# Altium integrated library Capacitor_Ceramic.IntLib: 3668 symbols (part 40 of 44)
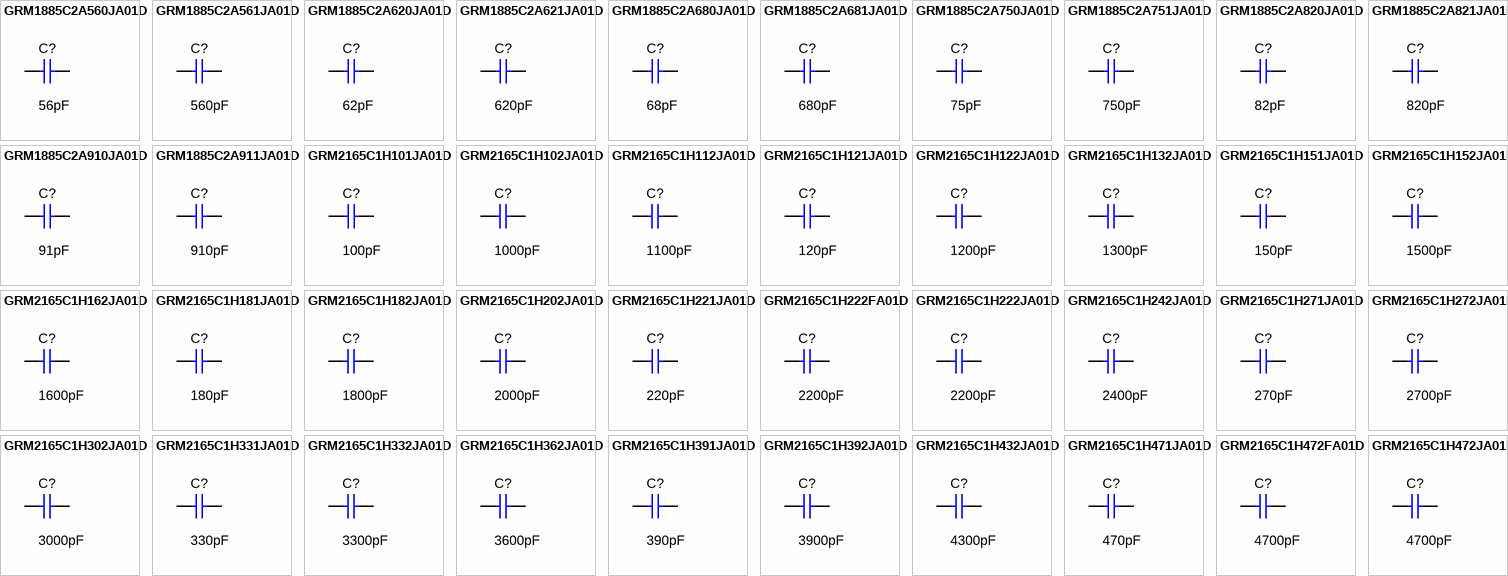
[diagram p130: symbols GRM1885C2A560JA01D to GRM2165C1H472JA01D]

## GRM2165C1H472JA01D
designator C?  ValueDisplayed: 4700pF  (hidden comment: GRM2165C1H472JA01D)
CAP, CERM, 4700 pF, 50 V,+/- 5%, C0G/NP0, 0805; Manufacturer: MuRata; Polarized: N; CompType: Capacitor; Value: 4700pF; U/M: EA; Cap_F: 0.0000000047; Tolerance_%: 5; VDC_V: 50; Value2: 50V; TaMin_C: -55; TaMax_C: 125; Cap_Case: 0805; SizeArea_mm2: 2.5; SizeAreaWB_mm2: 6.75; SizeX_mm: 2; SizeY_mm: 1.25; SizeZ_mm: 1.45; AEC Category: Q200
signal-integrity model Cap
simulation model Cap
footprint 0805_HV
footprint 0805_HV1
footprint 0805
footprint 0805M
footprint 0805L
pins: 1, 2

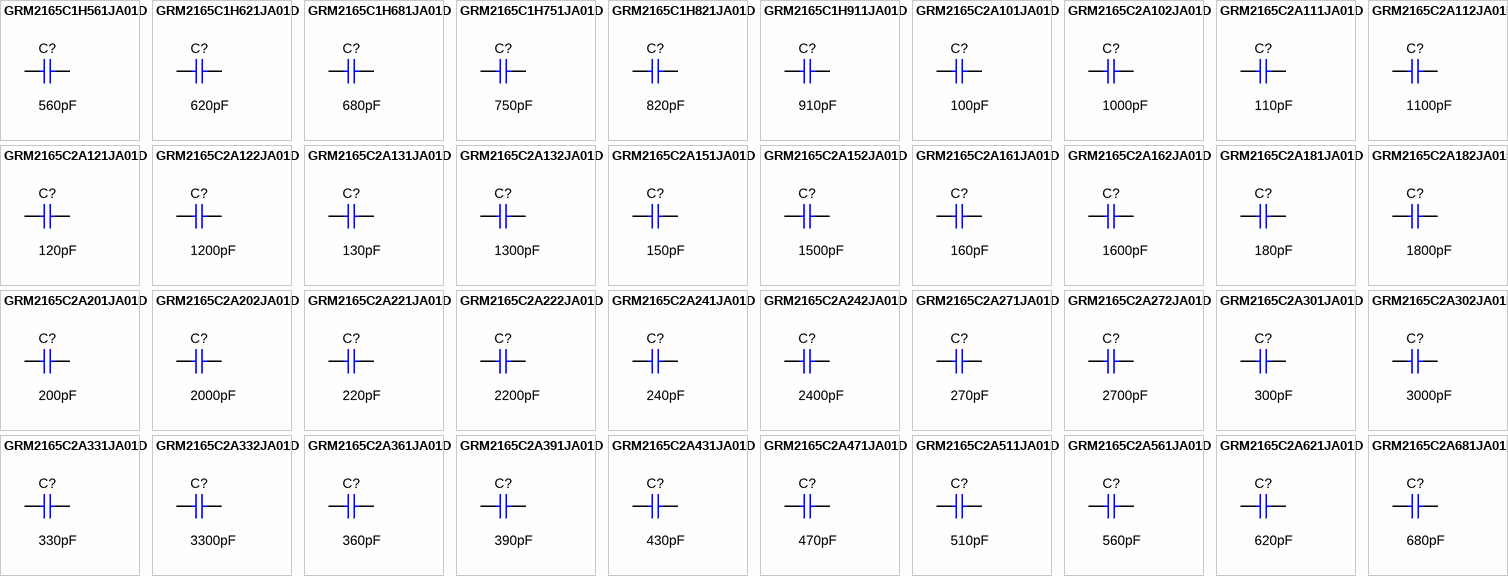
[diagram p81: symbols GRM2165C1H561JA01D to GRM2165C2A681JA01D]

## GRM2165C1H561JA01D
designator C?  ValueDisplayed: 560pF  (hidden comment: GRM2165C1H561JA01D)
CAP, CERM, 560 pF, 50 V,+/- 5%, C0G/NP0, 0805; Manufacturer: MuRata; Polarized: N; CompType: Capacitor; Value: 560pF; U/M: EA; Cap_F: 0.00000000056; Tolerance_%: 5; VDC_V: 50; Value2: 50V; TaMin_C: -55; TaMax_C: 125; Cap_Case: 0805; SizeArea_mm2: 2.5; SizeAreaWB_mm2: 6.75; SizeX_mm: 2; SizeY_mm: 1.25; SizeZ_mm: 1.45; AEC Category: Q200
signal-integrity model Cap
simulation model Cap
footprint 0805_HV
footprint 0805_HV1
footprint 0805
footprint 0805M
footprint 0805L
pins: 1, 2

## GRM2165C1H621JA01D
designator C?  ValueDisplayed: 620pF  (hidden comment: GRM2165C1H621JA01D)
CAP, CERM, 620 pF, 50 V,+/- 5%, C0G/NP0, 0805; Manufacturer: MuRata; Polarized: N; CompType: Capacitor; Value: 620pF; U/M: EA; Cap_F: 0.00000000062; Tolerance_%: 5; VDC_V: 50; Value2: 50V; TaMin_C: -55; TaMax_C: 125; Cap_Case: 0805; SizeArea_mm2: 2.5; SizeAreaWB_mm2: 6.75; SizeX_mm: 2; SizeY_mm: 1.25; SizeZ_mm: 1.45; AEC Category: Q200
signal-integrity model Cap
simulation model Cap
footprint 0805_HV
footprint 0805_HV1
footprint 0805
footprint 0805M
footprint 0805L
pins: 1, 2

## GRM2165C1H681JA01D
designator C?  ValueDisplayed: 680pF  (hidden comment: GRM2165C1H681JA01D)
CAP, CERM, 680 pF, 50 V,+/- 5%, C0G/NP0, 0805; Manufacturer: MuRata; Polarized: N; CompType: Capacitor; Value: 680pF; U/M: EA; Cap_F: 0.00000000068; Tolerance_%: 5; VDC_V: 50; Value2: 50V; TaMin_C: -55; TaMax_C: 125; Cap_Case: 0805; SizeArea_mm2: 2.5; SizeAreaWB_mm2: 6.75; SizeX_mm: 2; SizeY_mm: 1.25; SizeZ_mm: 1.45; AEC Category: Q200
signal-integrity model Cap
simulation model Cap
footprint 0805_HV
footprint 0805_HV1
footprint 0805
footprint 0805M
footprint 0805L
pins: 1, 2

## GRM2165C1H751JA01D
designator C?  ValueDisplayed: 750pF  (hidden comment: GRM2165C1H751JA01D)
CAP, CERM, 750 pF, 50 V,+/- 5%, C0G/NP0, 0805; Manufacturer: MuRata; Polarized: N; CompType: Capacitor; Value: 750pF; U/M: EA; Cap_F: 0.00000000075; Tolerance_%: 5; VDC_V: 50; Value2: 50V; TaMin_C: -55; TaMax_C: 125; Cap_Case: 0805; SizeArea_mm2: 2.5; SizeAreaWB_mm2: 6.75; SizeX_mm: 2; SizeY_mm: 1.25; SizeZ_mm: 1.45; AEC Category: Q200
signal-integrity model Cap
simulation model Cap
footprint 0805_HV
footprint 0805_HV1
footprint 0805
footprint 0805M
footprint 0805L
pins: 1, 2

## GRM2165C1H821JA01D
designator C?  ValueDisplayed: 820pF  (hidden comment: GRM2165C1H821JA01D)
CAP, CERM, 820 pF, 50 V,+/- 5%, C0G/NP0, 0805; Manufacturer: MuRata; Polarized: N; CompType: Capacitor; Value: 820pF; U/M: EA; Cap_F: 0.00000000082; Tolerance_%: 5; VDC_V: 50; Value2: 50V; TaMin_C: -55; TaMax_C: 125; Cap_Case: 0805; SizeArea_mm2: 2.5; SizeAreaWB_mm2: 6.75; SizeX_mm: 2; SizeY_mm: 1.25; SizeZ_mm: 1.45; AEC Category: Q200
signal-integrity model Cap
simulation model Cap
footprint 0805_HV
footprint 0805_HV1
footprint 0805
footprint 0805M
footprint 0805L
pins: 1, 2

## GRM2165C1H911JA01D
designator C?  ValueDisplayed: 910pF  (hidden comment: GRM2165C1H911JA01D)
CAP, CERM, 910 pF, 50 V,+/- 5%, C0G/NP0, 0805; Manufacturer: MuRata; Polarized: N; CompType: Capacitor; Value: 910pF; U/M: EA; Cap_F: 0.00000000091; Tolerance_%: 5; VDC_V: 50; Value2: 50V; TaMin_C: -55; TaMax_C: 125; Cap_Case: 0805; SizeArea_mm2: 2.5; SizeAreaWB_mm2: 6.75; SizeX_mm: 2; SizeY_mm: 1.25; SizeZ_mm: 1.45; AEC Category: Q200
signal-integrity model Cap
simulation model Cap
footprint 0805_HV
footprint 0805_HV1
footprint 0805
footprint 0805M
footprint 0805L
pins: 1, 2

## GRM2165C2A101JA01D
designator C?  ValueDisplayed: 100pF  (hidden comment: GRM2165C2A101JA01D)
CAP, CERM, 100 pF, 100 V,+/- 5%, C0G/NP0, 0805; Manufacturer: MuRata; Polarized: N; CompType: Capacitor; Value: 100pF; U/M: EA; Cap_F: 0.0000000001; Tolerance_%: 5; VDC_V: 100; Value2: 100V; TaMin_C: -55; TaMax_C: 125; Cap_Case: 0805; SizeArea_mm2: 2.5; SizeAreaWB_mm2: 6.75; SizeX_mm: 2; SizeY_mm: 1.25; SizeZ_mm: 1.45; AEC Category: Q200
signal-integrity model Cap
simulation model Cap
footprint 0805_HV
footprint 0805_HV1
footprint 0805
footprint 0805M
footprint 0805L
pins: 1, 2

## GRM2165C2A102JA01D
designator C?  ValueDisplayed: 1000pF  (hidden comment: GRM2165C2A102JA01D)
CAP, CERM, 1000 pF, 100 V,+/- 5%, C0G/NP0, 0805; Manufacturer: MuRata; Polarized: N; CompType: Capacitor; Value: 1000pF; U/M: EA; Cap_F: 0.000000001; Tolerance_%: 5; VDC_V: 100; Value2: 100V; TaMin_C: -55; TaMax_C: 125; Cap_Case: 0805; SizeArea_mm2: 2.5; SizeAreaWB_mm2: 6.75; SizeX_mm: 2; SizeY_mm: 1.25; SizeZ_mm: 1.45; AEC Category: Q200
signal-integrity model Cap
simulation model Cap
footprint 0805_HV
footprint 0805_HV1
footprint 0805
footprint 0805M
footprint 0805L
pins: 1, 2

## GRM2165C2A111JA01D
designator C?  ValueDisplayed: 110pF  (hidden comment: GRM2165C2A111JA01D)
CAP, CERM, 110 pF, 100 V,+/- 5%, C0G/NP0, 0805; Manufacturer: MuRata; Polarized: N; CompType: Capacitor; Value: 110pF; U/M: EA; Cap_F: 0.00000000011; Tolerance_%: 5; VDC_V: 100; Value2: 100V; TaMin_C: -55; TaMax_C: 125; Cap_Case: 0805; SizeArea_mm2: 2.5; SizeAreaWB_mm2: 6.75; SizeX_mm: 2; SizeY_mm: 1.25; SizeZ_mm: 1.45; AEC Category: Q200
signal-integrity model Cap
simulation model Cap
footprint 0805_HV
footprint 0805_HV1
footprint 0805
footprint 0805M
footprint 0805L
pins: 1, 2

## GRM2165C2A112JA01D
designator C?  ValueDisplayed: 1100pF  (hidden comment: GRM2165C2A112JA01D)
CAP, CERM, 1100 pF, 100 V,+/- 5%, C0G/NP0, 0805; Manufacturer: MuRata; Polarized: N; CompType: Capacitor; Value: 1100pF; U/M: EA; Cap_F: 0.0000000011; Tolerance_%: 5; VDC_V: 100; Value2: 100V; TaMin_C: -55; TaMax_C: 125; Cap_Case: 0805; SizeArea_mm2: 2.5; SizeAreaWB_mm2: 6.75; SizeX_mm: 2; SizeY_mm: 1.25; SizeZ_mm: 1.45; AEC Category: Q200
signal-integrity model Cap
simulation model Cap
footprint 0805_HV
footprint 0805_HV1
footprint 0805
footprint 0805M
footprint 0805L
pins: 1, 2

## GRM2165C2A121JA01D
designator C?  ValueDisplayed: 120pF  (hidden comment: GRM2165C2A121JA01D)
CAP, CERM, 120 pF, 100 V,+/- 5%, C0G/NP0, 0805; Manufacturer: MuRata; Polarized: N; CompType: Capacitor; Value: 120pF; U/M: EA; Cap_F: 0.00000000012; Tolerance_%: 5; VDC_V: 100; Value2: 100V; TaMin_C: -55; TaMax_C: 125; Cap_Case: 0805; SizeArea_mm2: 2.5; SizeAreaWB_mm2: 6.75; SizeX_mm: 2; SizeY_mm: 1.25; SizeZ_mm: 1.45; AEC Category: Q200
signal-integrity model Cap
simulation model Cap
footprint 0805_HV
footprint 0805_HV1
footprint 0805
footprint 0805M
footprint 0805L
pins: 1, 2

## GRM2165C2A122JA01D
designator C?  ValueDisplayed: 1200pF  (hidden comment: GRM2165C2A122JA01D)
CAP, CERM, 1200 pF, 100 V,+/- 5%, C0G/NP0, 0805; Manufacturer: MuRata; Polarized: N; CompType: Capacitor; Value: 1200pF; U/M: EA; Cap_F: 0.0000000012; Tolerance_%: 5; VDC_V: 100; Value2: 100V; TaMin_C: -55; TaMax_C: 125; Cap_Case: 0805; SizeArea_mm2: 2.5; SizeAreaWB_mm2: 6.75; SizeX_mm: 2; SizeY_mm: 1.25; SizeZ_mm: 1.45; AEC Category: Q200
signal-integrity model Cap
simulation model Cap
footprint 0805_HV
footprint 0805_HV1
footprint 0805
footprint 0805M
footprint 0805L
pins: 1, 2

## GRM2165C2A131JA01D
designator C?  ValueDisplayed: 130pF  (hidden comment: GRM2165C2A131JA01D)
CAP, CERM, 130 pF, 100 V,+/- 5%, C0G/NP0, 0805; Manufacturer: MuRata; Polarized: N; CompType: Capacitor; Value: 130pF; U/M: EA; Cap_F: 0.00000000013; Tolerance_%: 5; VDC_V: 100; Value2: 100V; TaMin_C: -55; TaMax_C: 125; Cap_Case: 0805; SizeArea_mm2: 2.5; SizeAreaWB_mm2: 6.75; SizeX_mm: 2; SizeY_mm: 1.25; SizeZ_mm: 1.45; AEC Category: Q200; Green_Lifecycle: Active; Green_REACh: Passed
signal-integrity model Cap
simulation model Cap
footprint 0805_HV
footprint 0805_HV1
footprint 0805
footprint 0805M
footprint 0805L
pins: 1, 2

## GRM2165C2A132JA01D
designator C?  ValueDisplayed: 1300pF  (hidden comment: GRM2165C2A132JA01D)
CAP, CERM, 1300 pF, 100 V,+/- 5%, C0G/NP0, 0805; Manufacturer: MuRata; Polarized: N; CompType: Capacitor; Value: 1300pF; U/M: EA; Cap_F: 0.0000000013; Tolerance_%: 5; VDC_V: 100; Value2: 100V; TaMin_C: -55; TaMax_C: 125; Cap_Case: 0805; SizeArea_mm2: 2.5; SizeAreaWB_mm2: 6.75; SizeX_mm: 2; SizeY_mm: 1.25; SizeZ_mm: 1.45; AEC Category: Q200
signal-integrity model Cap
simulation model Cap
footprint 0805_HV
footprint 0805_HV1
footprint 0805
footprint 0805M
footprint 0805L
pins: 1, 2

## GRM2165C2A151JA01D
designator C?  ValueDisplayed: 150pF  (hidden comment: GRM2165C2A151JA01D)
CAP, CERM, 150 pF, 100 V,+/- 5%, C0G/NP0, 0805; Manufacturer: MuRata; Polarized: N; CompType: Capacitor; Value: 150pF; U/M: EA; Cap_F: 0.00000000015; Tolerance_%: 5; VDC_V: 100; Value2: 100V; TaMin_C: -55; TaMax_C: 125; Cap_Case: 0805; SizeArea_mm2: 2.5; SizeAreaWB_mm2: 6.75; SizeX_mm: 2; SizeY_mm: 1.25; SizeZ_mm: 1.45; AEC Category: Q200
signal-integrity model Cap
simulation model Cap
footprint 0805_HV
footprint 0805_HV1
footprint 0805
footprint 0805M
footprint 0805L
pins: 1, 2

## GRM2165C2A152JA01D
designator C?  ValueDisplayed: 1500pF  (hidden comment: GRM2165C2A152JA01D)
CAP, CERM, 1500 pF, 100 V,+/- 5%, C0G/NP0, 0805; Manufacturer: MuRata; Polarized: N; CompType: Capacitor; Value: 1500pF; U/M: EA; Cap_F: 0.0000000015; Tolerance_%: 5; VDC_V: 100; Value2: 100V; TaMin_C: -55; TaMax_C: 125; Cap_Case: 0805; SizeArea_mm2: 2.5; SizeAreaWB_mm2: 6.75; SizeX_mm: 2; SizeY_mm: 1.25; SizeZ_mm: 1.45; AEC Category: Q200
signal-integrity model Cap
simulation model Cap
footprint 0805_HV
footprint 0805_HV1
footprint 0805
footprint 0805M
footprint 0805L
pins: 1, 2

## GRM2165C2A161JA01D
designator C?  ValueDisplayed: 160pF  (hidden comment: GRM2165C2A161JA01D)
CAP, CERM, 160 pF, 100 V,+/- 5%, C0G/NP0, 0805; Manufacturer: MuRata; Polarized: N; CompType: Capacitor; Value: 160pF; U/M: EA; Cap_F: 0.00000000016; Tolerance_%: 5; VDC_V: 100; Value2: 100V; TaMin_C: -55; TaMax_C: 125; Cap_Case: 0805; SizeArea_mm2: 2.5; SizeAreaWB_mm2: 6.75; SizeX_mm: 2; SizeY_mm: 1.25; SizeZ_mm: 1.45; AEC Category: Q200; Green_Lifecycle: Active; Green_REACh: Passed
signal-integrity model Cap
simulation model Cap
footprint 0805_HV
footprint 0805_HV1
footprint 0805
footprint 0805M
footprint 0805L
pins: 1, 2

## GRM2165C2A162JA01D
designator C?  ValueDisplayed: 1600pF  (hidden comment: GRM2165C2A162JA01D)
CAP, CERM, 1600 pF, 100 V,+/- 5%, C0G/NP0, 0805; Manufacturer: MuRata; Polarized: N; CompType: Capacitor; Value: 1600pF; U/M: EA; Cap_F: 0.0000000016; Tolerance_%: 5; VDC_V: 100; Value2: 100V; TaMin_C: -55; TaMax_C: 125; Cap_Case: 0805; SizeArea_mm2: 2.5; SizeAreaWB_mm2: 6.75; SizeX_mm: 2; SizeY_mm: 1.25; SizeZ_mm: 1.45; AEC Category: Q200
signal-integrity model Cap
simulation model Cap
footprint 0805_HV
footprint 0805_HV1
footprint 0805
footprint 0805M
footprint 0805L
pins: 1, 2

## GRM2165C2A181JA01D
designator C?  ValueDisplayed: 180pF  (hidden comment: GRM2165C2A181JA01D)
CAP, CERM, 180 pF, 100 V,+/- 5%, C0G/NP0, 0805; Manufacturer: MuRata; Polarized: N; CompType: Capacitor; Value: 180pF; U/M: EA; Cap_F: 0.00000000018; Tolerance_%: 5; VDC_V: 100; Value2: 100V; TaMin_C: -55; TaMax_C: 125; Cap_Case: 0805; SizeArea_mm2: 2.5; SizeAreaWB_mm2: 6.75; SizeX_mm: 2; SizeY_mm: 1.25; SizeZ_mm: 1.45; AEC Category: Q200
signal-integrity model Cap
simulation model Cap
footprint 0805_HV
footprint 0805_HV1
footprint 0805
footprint 0805M
footprint 0805L
pins: 1, 2

## GRM2165C2A182JA01D
designator C?  ValueDisplayed: 1800pF  (hidden comment: GRM2165C2A182JA01D)
CAP, CERM, 1800 pF, 100 V,+/- 5%, C0G/NP0, 0805; Manufacturer: MuRata; Polarized: N; CompType: Capacitor; Value: 1800pF; U/M: EA; Cap_F: 0.0000000018; Tolerance_%: 5; VDC_V: 100; Value2: 100V; TaMin_C: -55; TaMax_C: 125; Cap_Case: 0805; SizeArea_mm2: 2.5; SizeAreaWB_mm2: 6.75; SizeX_mm: 2; SizeY_mm: 1.25; SizeZ_mm: 1.45; AEC Category: Q200
signal-integrity model Cap
simulation model Cap
footprint 0805_HV
footprint 0805_HV1
footprint 0805
footprint 0805M
footprint 0805L
pins: 1, 2

## GRM2165C2A201JA01D
designator C?  ValueDisplayed: 200pF  (hidden comment: GRM2165C2A201JA01D)
CAP, CERM, 200 pF, 100 V,+/- 5%, C0G/NP0, 0805; Manufacturer: MuRata; Polarized: N; CompType: Capacitor; Value: 200pF; U/M: EA; Cap_F: 0.0000000002; Tolerance_%: 5; VDC_V: 100; Value2: 100V; TaMin_C: -55; TaMax_C: 125; Cap_Case: 0805; SizeArea_mm2: 2.5; SizeAreaWB_mm2: 6.75; SizeX_mm: 2; SizeY_mm: 1.25; SizeZ_mm: 1.45; AEC Category: Q200
signal-integrity model Cap
simulation model Cap
footprint 0805_HV
footprint 0805_HV1
footprint 0805
footprint 0805M
footprint 0805L
pins: 1, 2

## GRM2165C2A202JA01D
designator C?  ValueDisplayed: 2000pF  (hidden comment: GRM2165C2A202JA01D)
CAP, CERM, 2000 pF, 100 V,+/- 5%, C0G/NP0, 0805; Manufacturer: MuRata; Polarized: N; CompType: Capacitor; Value: 2000pF; U/M: EA; Cap_F: 0.000000002; Tolerance_%: 5; VDC_V: 100; Value2: 100V; TaMin_C: -55; TaMax_C: 125; Cap_Case: 0805; SizeArea_mm2: 2.5; SizeAreaWB_mm2: 6.75; SizeX_mm: 2; SizeY_mm: 1.25; SizeZ_mm: 1.45; AEC Category: Q200
signal-integrity model Cap
simulation model Cap
footprint 0805_HV
footprint 0805_HV1
footprint 0805
footprint 0805M
footprint 0805L
pins: 1, 2

## GRM2165C2A221JA01D
designator C?  ValueDisplayed: 220pF  (hidden comment: GRM2165C2A221JA01D)
CAP, CERM, 220 pF, 100 V,+/- 5%, C0G/NP0, 0805; Manufacturer: MuRata; Polarized: N; CompType: Capacitor; Value: 220pF; U/M: EA; Cap_F: 0.00000000022; Tolerance_%: 5; VDC_V: 100; Value2: 100V; TaMin_C: -55; TaMax_C: 125; Cap_Case: 0805; SizeArea_mm2: 2.5; SizeAreaWB_mm2: 6.75; SizeX_mm: 2; SizeY_mm: 1.25; SizeZ_mm: 1.45; AEC Category: Q200
signal-integrity model Cap
simulation model Cap
footprint 0805_HV
footprint 0805_HV1
footprint 0805
footprint 0805M
footprint 0805L
pins: 1, 2

## GRM2165C2A222JA01D
designator C?  ValueDisplayed: 2200pF  (hidden comment: GRM2165C2A222JA01D)
CAP, CERM, 2200 pF, 100 V,+/- 5%, C0G/NP0, 0805; Manufacturer: MuRata; Polarized: N; CompType: Capacitor; Value: 2200pF; U/M: EA; Cap_F: 0.0000000022; Tolerance_%: 5; VDC_V: 100; Value2: 100V; TaMin_C: -55; TaMax_C: 125; Cap_Case: 0805; SizeArea_mm2: 2.5; SizeAreaWB_mm2: 6.75; SizeX_mm: 2; SizeY_mm: 1.25; SizeZ_mm: 1.45; AEC Category: Q200
signal-integrity model Cap
simulation model Cap
footprint 0805_HV
footprint 0805_HV1
footprint 0805
footprint 0805M
footprint 0805L
pins: 1, 2

## GRM2165C2A241JA01D
designator C?  ValueDisplayed: 240pF  (hidden comment: GRM2165C2A241JA01D)
CAP, CERM, 240 pF, 100 V,+/- 5%, C0G/NP0, 0805; Manufacturer: MuRata; Polarized: N; CompType: Capacitor; Value: 240pF; U/M: EA; Cap_F: 0.00000000024; Tolerance_%: 5; VDC_V: 100; Value2: 100V; TaMin_C: -55; TaMax_C: 125; Cap_Case: 0805; SizeArea_mm2: 2.5; SizeAreaWB_mm2: 6.75; SizeX_mm: 2; SizeY_mm: 1.25; SizeZ_mm: 1.45; AEC Category: Q200
signal-integrity model Cap
simulation model Cap
footprint 0805_HV
footprint 0805_HV1
footprint 0805
footprint 0805M
footprint 0805L
pins: 1, 2

## GRM2165C2A242JA01D
designator C?  ValueDisplayed: 2400pF  (hidden comment: GRM2165C2A242JA01D)
CAP, CERM, 2400 pF, 100 V,+/- 5%, C0G/NP0, 0805; Manufacturer: MuRata; Polarized: N; CompType: Capacitor; Value: 2400pF; U/M: EA; Cap_F: 0.0000000024; Tolerance_%: 5; VDC_V: 100; Value2: 100V; TaMin_C: -55; TaMax_C: 125; Cap_Case: 0805; SizeArea_mm2: 2.5; SizeAreaWB_mm2: 6.75; SizeX_mm: 2; SizeY_mm: 1.25; SizeZ_mm: 1.45; AEC Category: Q200
signal-integrity model Cap
simulation model Cap
footprint 0805_HV
footprint 0805_HV1
footprint 0805
footprint 0805M
footprint 0805L
pins: 1, 2

## GRM2165C2A271JA01D
designator C?  ValueDisplayed: 270pF  (hidden comment: GRM2165C2A271JA01D)
CAP, CERM, 270 pF, 100 V,+/- 5%, C0G/NP0, 0805; Manufacturer: MuRata; Polarized: N; CompType: Capacitor; Value: 270pF; U/M: EA; Cap_F: 0.00000000027; Tolerance_%: 5; VDC_V: 100; Value2: 100V; TaMin_C: -55; TaMax_C: 125; Cap_Case: 0805; SizeArea_mm2: 2.5; SizeAreaWB_mm2: 6.75; SizeX_mm: 2; SizeY_mm: 1.25; SizeZ_mm: 1.45; AEC Category: Q200
signal-integrity model Cap
simulation model Cap
footprint 0805_HV
footprint 0805_HV1
footprint 0805
footprint 0805M
footprint 0805L
pins: 1, 2

## GRM2165C2A272JA01D
designator C?  ValueDisplayed: 2700pF  (hidden comment: GRM2165C2A272JA01D)
CAP, CERM, 2700 pF, 100 V,+/- 5%, C0G/NP0, 0805; Manufacturer: MuRata; Polarized: N; CompType: Capacitor; Value: 2700pF; U/M: EA; Cap_F: 0.0000000027; Tolerance_%: 5; VDC_V: 100; Value2: 100V; TaMin_C: -55; TaMax_C: 125; Cap_Case: 0805; SizeArea_mm2: 2.5; SizeAreaWB_mm2: 6.75; SizeX_mm: 2; SizeY_mm: 1.25; SizeZ_mm: 1.45; AEC Category: Q200
signal-integrity model Cap
simulation model Cap
footprint 0805_HV
footprint 0805_HV1
footprint 0805
footprint 0805M
footprint 0805L
pins: 1, 2

## GRM2165C2A301JA01D
designator C?  ValueDisplayed: 300pF  (hidden comment: GRM2165C2A301JA01D)
CAP, CERM, 300 pF, 100 V,+/- 5%, C0G/NP0, 0805; Manufacturer: MuRata; Polarized: N; CompType: Capacitor; Value: 300pF; U/M: EA; Cap_F: 0.0000000003; Tolerance_%: 5; VDC_V: 100; Value2: 100V; TaMin_C: -55; TaMax_C: 125; Cap_Case: 0805; SizeArea_mm2: 2.5; SizeAreaWB_mm2: 6.75; SizeX_mm: 2; SizeY_mm: 1.25; SizeZ_mm: 1.45; AEC Category: Q200
signal-integrity model Cap
simulation model Cap
footprint 0805_HV
footprint 0805_HV1
footprint 0805
footprint 0805M
footprint 0805L
pins: 1, 2

## GRM2165C2A302JA01D
designator C?  ValueDisplayed: 3000pF  (hidden comment: GRM2165C2A302JA01D)
CAP, CERM, 3000 pF, 100 V,+/- 5%, C0G/NP0, 0805; Manufacturer: MuRata; Polarized: N; CompType: Capacitor; Value: 3000pF; U/M: EA; Cap_F: 0.000000003; Tolerance_%: 5; VDC_V: 100; Value2: 100V; TaMin_C: -55; TaMax_C: 125; Cap_Case: 0805; SizeArea_mm2: 2.5; SizeAreaWB_mm2: 6.75; SizeX_mm: 2; SizeY_mm: 1.25; SizeZ_mm: 1.45; AEC Category: Q200
signal-integrity model Cap
simulation model Cap
footprint 0805_HV
footprint 0805_HV1
footprint 0805
footprint 0805M
footprint 0805L
pins: 1, 2

## GRM2165C2A331JA01D
designator C?  ValueDisplayed: 330pF  (hidden comment: GRM2165C2A331JA01D)
CAP, CERM, 330 pF, 100 V,+/- 5%, C0G/NP0, 0805; Manufacturer: MuRata; Polarized: N; CompType: Capacitor; Value: 330pF; U/M: EA; Cap_F: 0.00000000033; Tolerance_%: 5; VDC_V: 100; Value2: 100V; TaMin_C: -55; TaMax_C: 125; Cap_Case: 0805; SizeArea_mm2: 2.5; SizeAreaWB_mm2: 6.75; SizeX_mm: 2; SizeY_mm: 1.25; SizeZ_mm: 1.45; AEC Category: Q200
signal-integrity model Cap
simulation model Cap
footprint 0805_HV
footprint 0805_HV1
footprint 0805
footprint 0805M
footprint 0805L
pins: 1, 2

## GRM2165C2A332JA01D
designator C?  ValueDisplayed: 3300pF  (hidden comment: GRM2165C2A332JA01D)
CAP, CERM, 3300 pF, 100 V,+/- 5%, C0G/NP0, 0805; Manufacturer: MuRata; Polarized: N; CompType: Capacitor; Value: 3300pF; U/M: EA; Cap_F: 0.0000000033; Tolerance_%: 5; VDC_V: 100; Value2: 100V; TaMin_C: -55; TaMax_C: 125; Cap_Case: 0805; SizeArea_mm2: 2.5; SizeAreaWB_mm2: 6.75; SizeX_mm: 2; SizeY_mm: 1.25; SizeZ_mm: 1.45; AEC Category: Q200
signal-integrity model Cap
simulation model Cap
footprint 0805_HV
footprint 0805_HV1
footprint 0805
footprint 0805M
footprint 0805L
pins: 1, 2

## GRM2165C2A361JA01D
designator C?  ValueDisplayed: 360pF  (hidden comment: GRM2165C2A361JA01D)
CAP, CERM, 360 pF, 100 V,+/- 5%, C0G/NP0, 0805; Manufacturer: MuRata; Polarized: N; CompType: Capacitor; Value: 360pF; U/M: EA; Cap_F: 0.00000000036; Tolerance_%: 5; VDC_V: 100; Value2: 100V; TaMin_C: -55; TaMax_C: 125; Cap_Case: 0805; SizeArea_mm2: 2.5; SizeAreaWB_mm2: 6.75; SizeX_mm: 2; SizeY_mm: 1.25; SizeZ_mm: 1.45; AEC Category: Q200
signal-integrity model Cap
simulation model Cap
footprint 0805_HV
footprint 0805_HV1
footprint 0805
footprint 0805M
footprint 0805L
pins: 1, 2

## GRM2165C2A391JA01D
designator C?  ValueDisplayed: 390pF  (hidden comment: GRM2165C2A391JA01D)
CAP, CERM, 390 pF, 100 V,+/- 5%, C0G/NP0, 0805; Manufacturer: MuRata; Polarized: N; CompType: Capacitor; Value: 390pF; U/M: EA; Cap_F: 0.00000000039; Tolerance_%: 5; VDC_V: 100; Value2: 100V; TaMin_C: -55; TaMax_C: 125; Cap_Case: 0805; SizeArea_mm2: 2.5; SizeAreaWB_mm2: 6.75; SizeX_mm: 2; SizeY_mm: 1.25; SizeZ_mm: 1.45; AEC Category: Q200
signal-integrity model Cap
simulation model Cap
footprint 0805_HV
footprint 0805_HV1
footprint 0805
footprint 0805M
footprint 0805L
pins: 1, 2

## GRM2165C2A431JA01D
designator C?  ValueDisplayed: 430pF  (hidden comment: GRM2165C2A431JA01D)
CAP, CERM, 430 pF, 100 V,+/- 5%, C0G/NP0, 0805; Manufacturer: MuRata; Polarized: N; CompType: Capacitor; Value: 430pF; U/M: EA; Cap_F: 0.00000000043; Tolerance_%: 5; VDC_V: 100; Value2: 100V; TaMin_C: -55; TaMax_C: 125; Cap_Case: 0805; SizeArea_mm2: 2.5; SizeAreaWB_mm2: 6.75; SizeX_mm: 2; SizeY_mm: 1.25; SizeZ_mm: 1.45; AEC Category: Q200
signal-integrity model Cap
simulation model Cap
footprint 0805_HV
footprint 0805_HV1
footprint 0805
footprint 0805M
footprint 0805L
pins: 1, 2

## GRM2165C2A471JA01D
designator C?  ValueDisplayed: 470pF  (hidden comment: GRM2165C2A471JA01D)
CAP, CERM, 470 pF, 100 V,+/- 5%, C0G/NP0, 0805; Manufacturer: MuRata; Polarized: N; CompType: Capacitor; Value: 470pF; U/M: EA; Cap_F: 0.00000000047; Tolerance_%: 5; VDC_V: 100; Value2: 100V; TaMin_C: -55; TaMax_C: 125; Cap_Case: 0805; SizeArea_mm2: 2.5; SizeAreaWB_mm2: 6.75; SizeX_mm: 2; SizeY_mm: 1.25; SizeZ_mm: 1.45; AEC Category: Q200; Green_Lifecycle: Active; Green_REACh: Passed
signal-integrity model Cap
simulation model Cap
footprint 0805_HV
footprint 0805_HV1
footprint 0805
footprint 0805M
footprint 0805L
pins: 1, 2

## GRM2165C2A511JA01D
designator C?  ValueDisplayed: 510pF  (hidden comment: GRM2165C2A511JA01D)
CAP, CERM, 510 pF, 100 V,+/- 5%, C0G/NP0, 0805; Manufacturer: MuRata; Polarized: N; CompType: Capacitor; Value: 510pF; U/M: EA; Cap_F: 0.00000000051; Tolerance_%: 5; VDC_V: 100; Value2: 100V; TaMin_C: -55; TaMax_C: 125; Cap_Case: 0805; SizeArea_mm2: 2.5; SizeAreaWB_mm2: 6.75; SizeX_mm: 2; SizeY_mm: 1.25; SizeZ_mm: 1.45; AEC Category: Q200
signal-integrity model Cap
simulation model Cap
footprint 0805_HV
footprint 0805_HV1
footprint 0805
footprint 0805M
footprint 0805L
pins: 1, 2

## GRM2165C2A561JA01D
designator C?  ValueDisplayed: 560pF  (hidden comment: GRM2165C2A561JA01D)
CAP, CERM, 560 pF, 100 V,+/- 5%, C0G/NP0, 0805; Manufacturer: MuRata; Polarized: N; CompType: Capacitor; Value: 560pF; U/M: EA; Cap_F: 0.00000000056; Tolerance_%: 5; VDC_V: 100; Value2: 100V; TaMin_C: -55; TaMax_C: 125; Cap_Case: 0805; SizeArea_mm2: 2.5; SizeAreaWB_mm2: 6.75; SizeX_mm: 2; SizeY_mm: 1.25; SizeZ_mm: 1.45; AEC Category: Q200
signal-integrity model Cap
simulation model Cap
footprint 0805_HV
footprint 0805_HV1
footprint 0805
footprint 0805M
footprint 0805L
pins: 1, 2

## GRM2165C2A621JA01D
designator C?  ValueDisplayed: 620pF  (hidden comment: GRM2165C2A621JA01D)
CAP, CERM, 620 pF, 100 V,+/- 5%, C0G/NP0, 0805; Manufacturer: MuRata; Polarized: N; CompType: Capacitor; Value: 620pF; U/M: EA; Cap_F: 0.00000000062; Tolerance_%: 5; VDC_V: 100; Value2: 100V; TaMin_C: -55; TaMax_C: 125; Cap_Case: 0805; SizeArea_mm2: 2.5; SizeAreaWB_mm2: 6.75; SizeX_mm: 2; SizeY_mm: 1.25; SizeZ_mm: 1.45; AEC Category: Q200
signal-integrity model Cap
simulation model Cap
footprint 0805_HV
footprint 0805_HV1
footprint 0805
footprint 0805M
footprint 0805L
pins: 1, 2

## GRM2165C2A681JA01D
designator C?  ValueDisplayed: 680pF  (hidden comment: GRM2165C2A681JA01D)
CAP, CERM, 680 pF, 100 V,+/- 5%, C0G/NP0, 0805; Manufacturer: MuRata; Polarized: N; CompType: Capacitor; Value: 680pF; U/M: EA; Cap_F: 0.00000000068; Tolerance_%: 5; VDC_V: 100; Value2: 100V; TaMin_C: -55; TaMax_C: 125; Cap_Case: 0805; SizeArea_mm2: 2.5; SizeAreaWB_mm2: 6.75; SizeX_mm: 2; SizeY_mm: 1.25; SizeZ_mm: 1.45; AEC Category: Q200
signal-integrity model Cap
simulation model Cap
footprint 0805_HV
footprint 0805_HV1
footprint 0805
footprint 0805M
footprint 0805L
pins: 1, 2

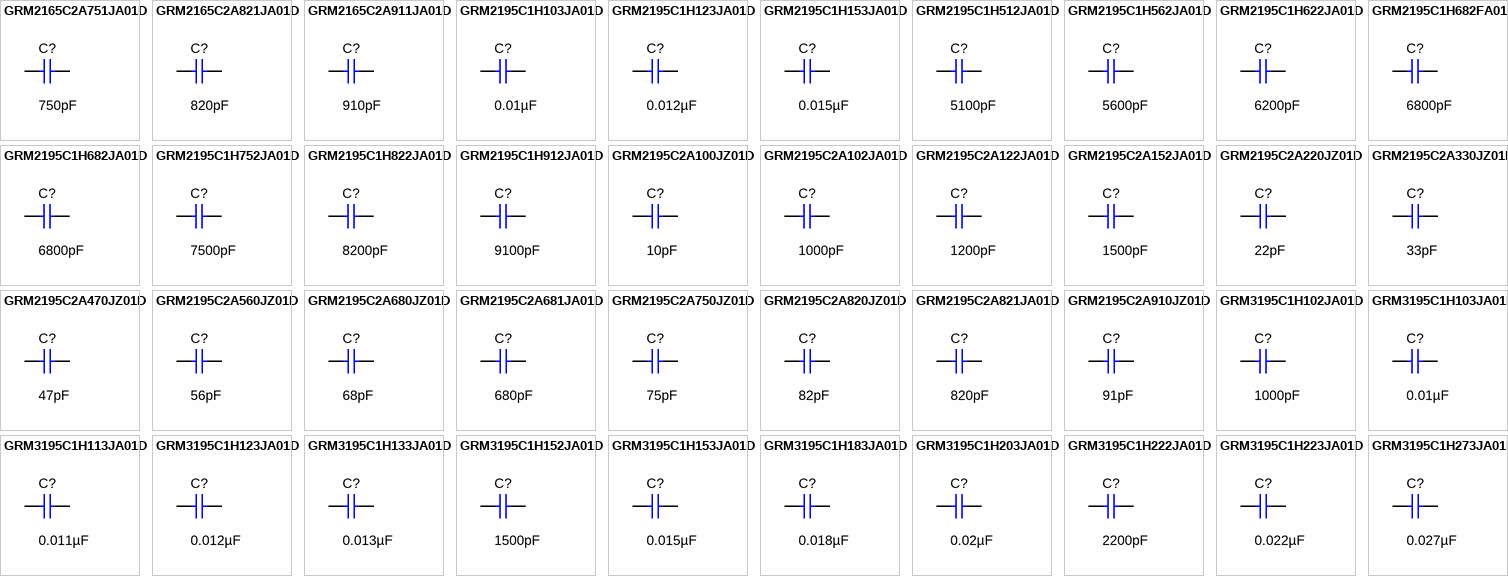
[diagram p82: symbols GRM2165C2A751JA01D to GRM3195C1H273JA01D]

## GRM2165C2A751JA01D
designator C?  ValueDisplayed: 750pF  (hidden comment: GRM2165C2A751JA01D)
CAP, CERM, 750 pF, 100 V,+/- 5%, C0G/NP0, 0805; Manufacturer: MuRata; Polarized: N; CompType: Capacitor; Value: 750pF; U/M: EA; Cap_F: 0.00000000075; Tolerance_%: 5; VDC_V: 100; Value2: 100V; TaMin_C: -55; TaMax_C: 125; Cap_Case: 0805; SizeArea_mm2: 2.5; SizeAreaWB_mm2: 6.75; SizeX_mm: 2; SizeY_mm: 1.25; SizeZ_mm: 1.45; AEC Category: Q200
signal-integrity model Cap
simulation model Cap
footprint 0805_HV
footprint 0805_HV1
footprint 0805
footprint 0805M
footprint 0805L
pins: 1, 2

## GRM2165C2A821JA01D
designator C?  ValueDisplayed: 820pF  (hidden comment: GRM2165C2A821JA01D)
CAP, CERM, 820 pF, 100 V,+/- 5%, C0G/NP0, 0805; Manufacturer: MuRata; Polarized: N; CompType: Capacitor; Value: 820pF; U/M: EA; Cap_F: 0.00000000082; Tolerance_%: 5; VDC_V: 100; Value2: 100V; TaMin_C: -55; TaMax_C: 125; Cap_Case: 0805; SizeArea_mm2: 2.5; SizeAreaWB_mm2: 6.75; SizeX_mm: 2; SizeY_mm: 1.25; SizeZ_mm: 1.45; AEC Category: Q200
signal-integrity model Cap
simulation model Cap
footprint 0805_HV
footprint 0805_HV1
footprint 0805
footprint 0805M
footprint 0805L
pins: 1, 2

## GRM2165C2A911JA01D
designator C?  ValueDisplayed: 910pF  (hidden comment: GRM2165C2A911JA01D)
CAP, CERM, 910 pF, 100 V,+/- 5%, C0G/NP0, 0805; Manufacturer: MuRata; Polarized: N; CompType: Capacitor; Value: 910pF; U/M: EA; Cap_F: 0.00000000091; Tolerance_%: 5; VDC_V: 100; Value2: 100V; TaMin_C: -55; TaMax_C: 125; Cap_Case: 0805; SizeArea_mm2: 2.5; SizeAreaWB_mm2: 6.75; SizeX_mm: 2; SizeY_mm: 1.25; SizeZ_mm: 1.45; AEC Category: Q200
signal-integrity model Cap
simulation model Cap
footprint 0805_HV
footprint 0805_HV1
footprint 0805
footprint 0805M
footprint 0805L
pins: 1, 2

## GRM2195C1H103JA01D
designator C?  ValueDisplayed: 0.01µF  (hidden comment: GRM2195C1H103JA01D)
CAP, CERM, 0.01 µF, 50 V,+/- 5%, C0G/NP0, 0805; Manufacturer: MuRata; Polarized: N; CompType: Capacitor; Value: 0.01uF; U/M: EA; Cap_F: 0.00000001; Tolerance_%: 5; VDC_V: 50; Value2: 50V; TaMin_C: -55; TaMax_C: 125; Cap_Case: 0805; SizeArea_mm2: 2.5; SizeAreaWB_mm2: 6.75; SizeX_mm: 2; SizeY_mm: 1.25; SizeZ_mm: 1.45; AEC Category: Q200; Green_Lifecycle: Active; Green_REACh: Passed
signal-integrity model Cap
simulation model Cap
footprint 0805_HV
footprint 0805_HV1
footprint 0805
footprint 0805M
footprint 0805L
pins: 1, 2

## GRM2195C1H123JA01D
designator C?  ValueDisplayed: 0.012µF  (hidden comment: GRM2195C1H123JA01D)
CAP, CERM, 0.012 µF, 50 V,+/- 5%, C0G/NP0, 0805; Manufacturer: MuRata; Polarized: N; CompType: Capacitor; Value: 0.012uF; U/M: EA; Cap_F: 0.000000012; Tolerance_%: 5; VDC_V: 50; Value2: 50V; TaMin_C: -55; TaMax_C: 125; Cap_Case: 0805; SizeArea_mm2: 2.5; SizeAreaWB_mm2: 6.75; SizeX_mm: 2; SizeY_mm: 1.25; SizeZ_mm: 1.45; AEC Category: Q200
signal-integrity model Cap
simulation model Cap
footprint 0805_HV
footprint 0805_HV1
footprint 0805
footprint 0805M
footprint 0805L
pins: 1, 2

## GRM2195C1H153JA01D
designator C?  ValueDisplayed: 0.015µF  (hidden comment: GRM2195C1H153JA01D)
CAP, CERM, 0.015 µF, 50 V,+/- 5%, C0G/NP0, 0805; Manufacturer: MuRata; Polarized: N; CompType: Capacitor; Value: 0.015uF; U/M: EA; Cap_F: 0.000000015; Tolerance_%: 5; VDC_V: 50; Value2: 50V; TaMin_C: -55; TaMax_C: 125; Cap_Case: 0805; SizeArea_mm2: 2.5; SizeAreaWB_mm2: 6.75; SizeX_mm: 2; SizeY_mm: 1.25; SizeZ_mm: 1.45; AEC Category: Q200
signal-integrity model Cap
simulation model Cap
footprint 0805_HV
footprint 0805_HV1
footprint 0805
footprint 0805M
footprint 0805L
pins: 1, 2

## GRM2195C1H512JA01D
designator C?  ValueDisplayed: 5100pF  (hidden comment: GRM2195C1H512JA01D)
CAP, CERM, 5100 pF, 50 V,+/- 5%, C0G/NP0, 0805; Manufacturer: MuRata; Polarized: N; CompType: Capacitor; Value: 5100pF; U/M: EA; Cap_F: 0.0000000051; Tolerance_%: 5; VDC_V: 50; Value2: 50V; TaMin_C: -55; TaMax_C: 125; Cap_Case: 0805; SizeArea_mm2: 2.5; SizeAreaWB_mm2: 6.75; SizeX_mm: 2; SizeY_mm: 1.25; SizeZ_mm: 1.45; AEC Category: Q200
signal-integrity model Cap
simulation model Cap
footprint 0805_HV
footprint 0805_HV1
footprint 0805
footprint 0805M
footprint 0805L
pins: 1, 2

## GRM2195C1H562JA01D
designator C?  ValueDisplayed: 5600pF  (hidden comment: GRM2195C1H562JA01D)
CAP, CERM, 5600 pF, 50 V,+/- 5%, C0G/NP0, 0805; Manufacturer: MuRata; Polarized: N; CompType: Capacitor; Value: 5600pF; U/M: EA; Cap_F: 0.0000000056; Tolerance_%: 5; VDC_V: 50; Value2: 50V; TaMin_C: -55; TaMax_C: 125; Cap_Case: 0805; SizeArea_mm2: 2.5; SizeAreaWB_mm2: 6.75; SizeX_mm: 2; SizeY_mm: 1.25; SizeZ_mm: 1.45; AEC Category: Q200
signal-integrity model Cap
simulation model Cap
footprint 0805_HV
footprint 0805_HV1
footprint 0805
footprint 0805M
footprint 0805L
pins: 1, 2

## GRM2195C1H622JA01D
designator C?  ValueDisplayed: 6200pF  (hidden comment: GRM2195C1H622JA01D)
CAP, CERM, 6200 pF, 50 V,+/- 5%, C0G/NP0, 0805; Manufacturer: MuRata; Polarized: N; CompType: Capacitor; Value: 6200pF; U/M: EA; Cap_F: 0.0000000062; Tolerance_%: 5; VDC_V: 50; Value2: 50V; TaMin_C: -55; TaMax_C: 125; Cap_Case: 0805; SizeArea_mm2: 2.5; SizeAreaWB_mm2: 6.75; SizeX_mm: 2; SizeY_mm: 1.25; SizeZ_mm: 1.45; AEC Category: Q200
signal-integrity model Cap
simulation model Cap
footprint 0805_HV
footprint 0805_HV1
footprint 0805
footprint 0805M
footprint 0805L
pins: 1, 2

## GRM2195C1H682FA01D
designator C?  ValueDisplayed: 6800pF  (hidden comment: GRM2195C1H682FA01D)
CAP, CERM, 6800 pF, 50 V,+/- 1%, C0G/NP0, 0805; Manufacturer: MuRata; Polarized: N; CompType: Capacitor; Value: 6800pF; U/M: EA; Cap_F: 0.0000000068; Tolerance_%: 1; VDC_V: 50; Value2: 50V; TaMin_C: -55; TaMax_C: 125; Cap_Case: 0805; SizeArea_mm2: 2.5; SizeAreaWB_mm2: 6.75; SizeX_mm: 2; SizeY_mm: 1.25; SizeZ_mm: 1.45; AEC Category: Q200
signal-integrity model Cap
simulation model Cap
footprint 0805_HV
footprint 0805_HV1
footprint 0805
footprint 0805M
footprint 0805L
pins: 1, 2

## GRM2195C1H682JA01D
designator C?  ValueDisplayed: 6800pF  (hidden comment: GRM2195C1H682JA01D)
CAP, CERM, 6800 pF, 50 V,+/- 5%, C0G/NP0, 0805; Manufacturer: MuRata; Polarized: N; CompType: Capacitor; Value: 6800pF; U/M: EA; Cap_F: 0.0000000068; Tolerance_%: 5; VDC_V: 50; Value2: 50V; TaMin_C: -55; TaMax_C: 125; Cap_Case: 0805; SizeArea_mm2: 2.5; SizeAreaWB_mm2: 6.75; SizeX_mm: 2; SizeY_mm: 1.25; SizeZ_mm: 1.45; AEC Category: Q200
signal-integrity model Cap
simulation model Cap
footprint 0805_HV
footprint 0805_HV1
footprint 0805
footprint 0805M
footprint 0805L
pins: 1, 2

## GRM2195C1H752JA01D
designator C?  ValueDisplayed: 7500pF  (hidden comment: GRM2195C1H752JA01D)
CAP, CERM, 7500 pF, 50 V,+/- 5%, C0G/NP0, 0805; Manufacturer: MuRata; Polarized: N; CompType: Capacitor; Value: 7500pF; U/M: EA; Cap_F: 0.0000000075; Tolerance_%: 5; VDC_V: 50; Value2: 50V; TaMin_C: -55; TaMax_C: 125; Cap_Case: 0805; SizeArea_mm2: 2.5; SizeAreaWB_mm2: 6.75; SizeX_mm: 2; SizeY_mm: 1.25; SizeZ_mm: 1.45; AEC Category: Q200
signal-integrity model Cap
simulation model Cap
footprint 0805_HV
footprint 0805_HV1
footprint 0805
footprint 0805M
footprint 0805L
pins: 1, 2

## GRM2195C1H822JA01D
designator C?  ValueDisplayed: 8200pF  (hidden comment: GRM2195C1H822JA01D)
CAP, CERM, 8200 pF, 50 V,+/- 5%, C0G/NP0, 0805; Manufacturer: MuRata; Polarized: N; CompType: Capacitor; Value: 8200pF; U/M: EA; Cap_F: 0.0000000082; Tolerance_%: 5; VDC_V: 50; Value2: 50V; TaMin_C: -55; TaMax_C: 125; Cap_Case: 0805; SizeArea_mm2: 2.5; SizeAreaWB_mm2: 6.75; SizeX_mm: 2; SizeY_mm: 1.25; SizeZ_mm: 1.45; AEC Category: Q200
signal-integrity model Cap
simulation model Cap
footprint 0805_HV
footprint 0805_HV1
footprint 0805
footprint 0805M
footprint 0805L
pins: 1, 2

## GRM2195C1H912JA01D
designator C?  ValueDisplayed: 9100pF  (hidden comment: GRM2195C1H912JA01D)
CAP, CERM, 9100 pF, 50 V,+/- 5%, C0G/NP0, 0805; Manufacturer: MuRata; Polarized: N; CompType: Capacitor; Value: 9100pF; U/M: EA; Cap_F: 0.0000000091; Tolerance_%: 5; VDC_V: 50; Value2: 50V; TaMin_C: -55; TaMax_C: 125; Cap_Case: 0805; SizeArea_mm2: 2.5; SizeAreaWB_mm2: 6.75; SizeX_mm: 2; SizeY_mm: 1.25; SizeZ_mm: 1.45; AEC Category: Q200
signal-integrity model Cap
simulation model Cap
footprint 0805_HV
footprint 0805_HV1
footprint 0805
footprint 0805M
footprint 0805L
pins: 1, 2

## GRM2195C2A100JZ01D
designator C?  ValueDisplayed: 10pF  (hidden comment: GRM2195C2A100JZ01D)
CAP, CERM, 10 pF, 100 V,+/- 5%, C0G/NP0, 0805; Manufacturer: MuRata; Polarized: N; CompType: Capacitor; Value: 10pF; U/M: EA; Cap_F: 0.00000000001; Tolerance_%: 5; VDC_V: 100; Value2: 100V; TaMin_C: -55; TaMax_C: 125; Cap_Case: 0805; SizeArea_mm2: 2.5; SizeAreaWB_mm2: 6.75; SizeX_mm: 2; SizeY_mm: 1.25; SizeZ_mm: 1.45; AEC Category: Q200
signal-integrity model Cap
simulation model Cap
footprint 0805_HV
footprint 0805_HV1
footprint 0805
footprint 0805M
footprint 0805L
pins: 1, 2

## GRM2195C2A102JA01D
designator C?  ValueDisplayed: 1000pF  (hidden comment: GRM2195C2A102JA01D)
CAP, CERM, 1000 pF, 100 V,+/- 5%, C0G/NP0, 0805; Manufacturer: MuRata; Polarized: N; CompType: Capacitor; Value: 1000pF; U/M: EA; Cap_F: 0.000000001; Tolerance_%: 5; VDC_V: 100; Value2: 100V; TaMin_C: -55; TaMax_C: 125; Cap_Case: 0805; SizeArea_mm2: 2.5; SizeAreaWB_mm2: 6.75; SizeX_mm: 2; SizeY_mm: 1.25; SizeZ_mm: 1.45; AEC Category: Q200; Green_Lifecycle: Active; Green_REACh: Passed
signal-integrity model Cap
simulation model Cap
footprint 0805_HV
footprint 0805_HV1
footprint 0805
footprint 0805M
footprint 0805L
pins: 1, 2

## GRM2195C2A122JA01D
designator C?  ValueDisplayed: 1200pF  (hidden comment: GRM2195C2A122JA01D)
CAP, CERM, 1200 pF, 100 V,+/- 5%, C0G/NP0, 0805; Manufacturer: MuRata; Polarized: N; CompType: Capacitor; Value: 1200pF; U/M: EA; Cap_F: 0.0000000012; Tolerance_%: 5; VDC_V: 100; Value2: 100V; TaMin_C: -55; TaMax_C: 125; Cap_Case: 0805; SizeArea_mm2: 2.5; SizeAreaWB_mm2: 6.75; SizeX_mm: 2; SizeY_mm: 1.25; SizeZ_mm: 1.45; AEC Category: Q200
signal-integrity model Cap
simulation model Cap
footprint 0805_HV
footprint 0805_HV1
footprint 0805
footprint 0805M
footprint 0805L
pins: 1, 2

## GRM2195C2A152JA01D
designator C?  ValueDisplayed: 1500pF  (hidden comment: GRM2195C2A152JA01D)
CAP, CERM, 1500 pF, 100 V,+/- 5%, C0G/NP0, 0805; Manufacturer: MuRata; Polarized: N; CompType: Capacitor; Value: 1500pF; U/M: EA; Cap_F: 0.0000000015; Tolerance_%: 5; VDC_V: 100; Value2: 100V; TaMin_C: -55; TaMax_C: 125; Cap_Case: 0805; SizeArea_mm2: 2.5; SizeAreaWB_mm2: 6.75; SizeX_mm: 2; SizeY_mm: 1.25; SizeZ_mm: 1.45; AEC Category: Q200
signal-integrity model Cap
simulation model Cap
footprint 0805_HV
footprint 0805_HV1
footprint 0805
footprint 0805M
footprint 0805L
pins: 1, 2

## GRM2195C2A220JZ01D
designator C?  ValueDisplayed: 22pF  (hidden comment: GRM2195C2A220JZ01D)
CAP, CERM, 22 pF, 100 V,+/- 5%, C0G/NP0, 0805; Manufacturer: MuRata; Polarized: N; CompType: Capacitor; Value: 22pF; U/M: EA; Cap_F: 0.000000000022; Tolerance_%: 5; VDC_V: 100; Value2: 100V; TaMin_C: -55; TaMax_C: 125; Cap_Case: 0805; SizeArea_mm2: 2.5; SizeAreaWB_mm2: 6.75; SizeX_mm: 2; SizeY_mm: 1.25; SizeZ_mm: 1.45; AEC Category: Q200
signal-integrity model Cap
simulation model Cap
footprint 0805_HV
footprint 0805_HV1
footprint 0805
footprint 0805M
footprint 0805L
pins: 1, 2

## GRM2195C2A330JZ01D
designator C?  ValueDisplayed: 33pF  (hidden comment: GRM2195C2A330JZ01D)
CAP, CERM, 33 pF, 100 V,+/- 5%, C0G/NP0, 0805; Manufacturer: MuRata; Polarized: N; CompType: Capacitor; Value: 33pF; U/M: EA; Cap_F: 0.000000000033; Tolerance_%: 5; VDC_V: 100; Value2: 100V; TaMin_C: -55; TaMax_C: 125; Cap_Case: 0805; SizeArea_mm2: 2.5; SizeAreaWB_mm2: 6.75; SizeX_mm: 2; SizeY_mm: 1.25; SizeZ_mm: 1.45; AEC Category: Q200
signal-integrity model Cap
simulation model Cap
footprint 0805_HV
footprint 0805_HV1
footprint 0805
footprint 0805M
footprint 0805L
pins: 1, 2

## GRM2195C2A470JZ01D
designator C?  ValueDisplayed: 47pF  (hidden comment: GRM2195C2A470JZ01D)
CAP, CERM, 47 pF, 100 V,+/- 5%, C0G/NP0, 0805; Manufacturer: MuRata; Polarized: N; CompType: Capacitor; Value: 47pF; U/M: EA; Cap_F: 0.000000000047; Tolerance_%: 5; VDC_V: 100; Value2: 100V; TaMin_C: -55; TaMax_C: 125; Cap_Case: 0805; SizeArea_mm2: 2.5; SizeAreaWB_mm2: 6.75; SizeX_mm: 2; SizeY_mm: 1.25; SizeZ_mm: 1.45; AEC Category: Q200
signal-integrity model Cap
simulation model Cap
footprint 0805_HV
footprint 0805_HV1
footprint 0805
footprint 0805M
footprint 0805L
pins: 1, 2

## GRM2195C2A560JZ01D
designator C?  ValueDisplayed: 56pF  (hidden comment: GRM2195C2A560JZ01D)
CAP, CERM, 56 pF, 100 V,+/- 5%, C0G/NP0, 0805; Manufacturer: MuRata; Polarized: N; CompType: Capacitor; Value: 56pF; U/M: EA; Cap_F: 0.000000000056; Tolerance_%: 5; VDC_V: 100; Value2: 100V; TaMin_C: -55; TaMax_C: 125; Cap_Case: 0805; SizeArea_mm2: 2.5; SizeAreaWB_mm2: 6.75; SizeX_mm: 2; SizeY_mm: 1.25; SizeZ_mm: 1.45; AEC Category: Q200
signal-integrity model Cap
simulation model Cap
footprint 0805_HV
footprint 0805_HV1
footprint 0805
footprint 0805M
footprint 0805L
pins: 1, 2

## GRM2195C2A680JZ01D
designator C?  ValueDisplayed: 68pF  (hidden comment: GRM2195C2A680JZ01D)
CAP, CERM, 68 pF, 100 V,+/- 5%, C0G/NP0, 0805; Manufacturer: MuRata; Polarized: N; CompType: Capacitor; Value: 68pF; U/M: EA; Cap_F: 0.000000000068; Tolerance_%: 5; VDC_V: 100; Value2: 100V; TaMin_C: -55; TaMax_C: 125; Cap_Case: 0805; SizeArea_mm2: 2.5; SizeAreaWB_mm2: 6.75; SizeX_mm: 2; SizeY_mm: 1.25; SizeZ_mm: 1.45; AEC Category: Q200
signal-integrity model Cap
simulation model Cap
footprint 0805_HV
footprint 0805_HV1
footprint 0805
footprint 0805M
footprint 0805L
pins: 1, 2

## GRM2195C2A681JA01D
designator C?  ValueDisplayed: 680pF  (hidden comment: GRM2195C2A681JA01D)
CAP, CERM, 680 pF, 100 V,+/- 5%, C0G/NP0, 0805; Manufacturer: MuRata; Polarized: N; CompType: Capacitor; Value: 680pF; U/M: EA; Cap_F: 0.00000000068; Tolerance_%: 5; VDC_V: 100; Value2: 100V; TaMin_C: -55; TaMax_C: 125; Cap_Case: 0805; SizeArea_mm2: 2.5; SizeAreaWB_mm2: 6.75; SizeX_mm: 2; SizeY_mm: 1.25; SizeZ_mm: 1.45; AEC Category: Q200
signal-integrity model Cap
simulation model Cap
footprint 0805_HV
footprint 0805_HV1
footprint 0805
footprint 0805M
footprint 0805L
pins: 1, 2

## GRM2195C2A750JZ01D
designator C?  ValueDisplayed: 75pF  (hidden comment: GRM2195C2A750JZ01D)
CAP, CERM, 75 pF, 100 V,+/- 5%, C0G/NP0, 0805; Manufacturer: MuRata; Polarized: N; CompType: Capacitor; Value: 75pF; U/M: EA; Cap_F: 0.000000000075; Tolerance_%: 5; VDC_V: 100; Value2: 100V; TaMin_C: -55; TaMax_C: 125; Cap_Case: 0805; SizeArea_mm2: 2.5; SizeAreaWB_mm2: 6.75; SizeX_mm: 2; SizeY_mm: 1.25; SizeZ_mm: 1.45; AEC Category: Q200
signal-integrity model Cap
simulation model Cap
footprint 0805_HV
footprint 0805_HV1
footprint 0805
footprint 0805M
footprint 0805L
pins: 1, 2

## GRM2195C2A820JZ01D
designator C?  ValueDisplayed: 82pF  (hidden comment: GRM2195C2A820JZ01D)
CAP, CERM, 82 pF, 100 V,+/- 5%, C0G/NP0, 0805; Manufacturer: MuRata; Polarized: N; CompType: Capacitor; Value: 82pF; U/M: EA; Cap_F: 0.000000000082; Tolerance_%: 5; VDC_V: 100; Value2: 100V; TaMin_C: -55; TaMax_C: 125; Cap_Case: 0805; SizeArea_mm2: 2.5; SizeAreaWB_mm2: 6.75; SizeX_mm: 2; SizeY_mm: 1.25; SizeZ_mm: 1.45; AEC Category: Q200
signal-integrity model Cap
simulation model Cap
footprint 0805_HV
footprint 0805_HV1
footprint 0805
footprint 0805M
footprint 0805L
pins: 1, 2

## GRM2195C2A821JA01D
designator C?  ValueDisplayed: 820pF  (hidden comment: GRM2195C2A821JA01D)
CAP, CERM, 820 pF, 100 V,+/- 5%, C0G/NP0, 0805; Manufacturer: MuRata; Polarized: N; CompType: Capacitor; Value: 820pF; U/M: EA; Cap_F: 0.00000000082; Tolerance_%: 5; VDC_V: 100; Value2: 100V; TaMin_C: -55; TaMax_C: 125; Cap_Case: 0805; SizeArea_mm2: 2.5; SizeAreaWB_mm2: 6.75; SizeX_mm: 2; SizeY_mm: 1.25; SizeZ_mm: 1.45; AEC Category: Q200
signal-integrity model Cap
simulation model Cap
footprint 0805_HV
footprint 0805_HV1
footprint 0805
footprint 0805M
footprint 0805L
pins: 1, 2

## GRM2195C2A910JZ01D
designator C?  ValueDisplayed: 91pF  (hidden comment: GRM2195C2A910JZ01D)
CAP, CERM, 91 pF, 100 V,+/- 5%, C0G/NP0, 0805; Manufacturer: MuRata; Polarized: N; CompType: Capacitor; Value: 91pF; U/M: EA; Cap_F: 0.000000000091; Tolerance_%: 5; VDC_V: 100; Value2: 100V; TaMin_C: -55; TaMax_C: 125; Cap_Case: 0805; SizeArea_mm2: 2.5; SizeAreaWB_mm2: 6.75; SizeX_mm: 2; SizeY_mm: 1.25; SizeZ_mm: 1.45; AEC Category: Q200
signal-integrity model Cap
simulation model Cap
footprint 0805_HV
footprint 0805_HV1
footprint 0805
footprint 0805M
footprint 0805L
pins: 1, 2

## GRM3195C1H102JA01D
designator C?  ValueDisplayed: 1000pF  (hidden comment: GRM3195C1H102JA01D)
CAP, CERM, 1000 pF, 50 V,+/- 5%, C0G/NP0, 1206; Manufacturer: MuRata; Polarized: N; CompType: Capacitor; Value: 1000pF; U/M: EA; Cap_F: 0.000000001; Tolerance_%: 5; VDC_V: 50; Value2: 50V; TaMin_C: -55; TaMax_C: 125; Cap_Case: 1206; SizeArea_mm2: 5.12; SizeAreaWB_mm2: 10.92; SizeX_mm: 3.2; SizeY_mm: 1.6; SizeZ_mm: 1.35; AEC Category: Q200; Green_Lifecycle: Active; Green_REACh: Passed
signal-integrity model Cap
simulation model Cap
footprint 1206
footprint 1206M
footprint 1206L
pins: 1, 2

## GRM3195C1H103JA01D
designator C?  ValueDisplayed: 0.01µF  (hidden comment: GRM3195C1H103JA01D)
CAP, CERM, 0.01 µF, 50 V,+/- 5%, C0G/NP0, 1206; Manufacturer: MuRata; Polarized: N; CompType: Capacitor; Value: 0.01uF; U/M: EA; Cap_F: 0.00000001; Tolerance_%: 5; VDC_V: 50; Value2: 50V; TaMin_C: -55; TaMax_C: 125; Cap_Case: 1206; SizeArea_mm2: 5.12; SizeAreaWB_mm2: 10.92; SizeX_mm: 3.2; SizeY_mm: 1.6; SizeZ_mm: 1.35; AEC Category: Q200
signal-integrity model Cap
simulation model Cap
footprint 1206
footprint 1206M
footprint 1206L
pins: 1, 2

## GRM3195C1H113JA01D
designator C?  ValueDisplayed: 0.011µF  (hidden comment: GRM3195C1H113JA01D)
CAP, CERM, 0.011 µF, 50 V,+/- 5%, C0G/NP0, 1206; Manufacturer: MuRata; Polarized: N; CompType: Capacitor; Value: 0.011uF; U/M: EA; Cap_F: 0.000000011; Tolerance_%: 5; VDC_V: 50; Value2: 50V; TaMin_C: -55; TaMax_C: 125; Cap_Case: 1206; SizeArea_mm2: 5.12; SizeAreaWB_mm2: 10.92; SizeX_mm: 3.2; SizeY_mm: 1.6; SizeZ_mm: 1.35; AEC Category: Q200
signal-integrity model Cap
simulation model Cap
footprint 1206
footprint 1206M
footprint 1206L
pins: 1, 2

## GRM3195C1H123JA01D
designator C?  ValueDisplayed: 0.012µF  (hidden comment: GRM3195C1H123JA01D)
CAP, CERM, 0.012 µF, 50 V,+/- 5%, C0G/NP0, 1206; Manufacturer: MuRata; Polarized: N; CompType: Capacitor; Value: 0.012uF; U/M: EA; Cap_F: 0.000000012; Tolerance_%: 5; VDC_V: 50; Value2: 50V; TaMin_C: -55; TaMax_C: 125; Cap_Case: 1206; SizeArea_mm2: 5.12; SizeAreaWB_mm2: 10.92; SizeX_mm: 3.2; SizeY_mm: 1.6; SizeZ_mm: 1.35; AEC Category: Q200
signal-integrity model Cap
simulation model Cap
footprint 1206
footprint 1206M
footprint 1206L
pins: 1, 2

## GRM3195C1H133JA01D
designator C?  ValueDisplayed: 0.013µF  (hidden comment: GRM3195C1H133JA01D)
CAP, CERM, 0.013 µF, 50 V,+/- 5%, C0G/NP0, 1206; Manufacturer: MuRata; Polarized: N; CompType: Capacitor; Value: 0.013uF; U/M: EA; Cap_F: 0.000000013; Tolerance_%: 5; VDC_V: 50; Value2: 50V; TaMin_C: -55; TaMax_C: 125; Cap_Case: 1206; SizeArea_mm2: 5.12; SizeAreaWB_mm2: 10.92; SizeX_mm: 3.2; SizeY_mm: 1.6; SizeZ_mm: 1.35; AEC Category: Q200
signal-integrity model Cap
simulation model Cap
footprint 1206
footprint 1206M
footprint 1206L
pins: 1, 2

## GRM3195C1H152JA01D
designator C?  ValueDisplayed: 1500pF  (hidden comment: GRM3195C1H152JA01D)
CAP, CERM, 1500 pF, 50 V,+/- 5%, C0G/NP0, 1206; Manufacturer: MuRata; Polarized: N; CompType: Capacitor; Value: 1500pF; U/M: EA; Cap_F: 0.0000000015; Tolerance_%: 5; VDC_V: 50; Value2: 50V; TaMin_C: -55; TaMax_C: 125; Cap_Case: 1206; SizeArea_mm2: 5.12; SizeAreaWB_mm2: 10.92; SizeX_mm: 3.2; SizeY_mm: 1.6; SizeZ_mm: 1.35; AEC Category: Q200
signal-integrity model Cap
simulation model Cap
footprint 1206
footprint 1206M
footprint 1206L
pins: 1, 2

## GRM3195C1H153JA01D
designator C?  ValueDisplayed: 0.015µF  (hidden comment: GRM3195C1H153JA01D)
CAP, CERM, 0.015 µF, 50 V,+/- 5%, C0G/NP0, 1206; Manufacturer: MuRata; Polarized: N; CompType: Capacitor; Value: 0.015uF; U/M: EA; Cap_F: 0.000000015; Tolerance_%: 5; VDC_V: 50; Value2: 50V; TaMin_C: -55; TaMax_C: 125; Cap_Case: 1206; SizeArea_mm2: 5.12; SizeAreaWB_mm2: 10.92; SizeX_mm: 3.2; SizeY_mm: 1.6; SizeZ_mm: 1.35; AEC Category: Q200; Green_Lifecycle: Active; Green_REACh: Passed
signal-integrity model Cap
simulation model Cap
footprint 1206
footprint 1206M
footprint 1206L
pins: 1, 2

## GRM3195C1H183JA01D
designator C?  ValueDisplayed: 0.018µF  (hidden comment: GRM3195C1H183JA01D)
CAP, CERM, 0.018 µF, 50 V,+/- 5%, C0G/NP0, 1206; Manufacturer: MuRata; Polarized: N; CompType: Capacitor; Value: 0.018uF; U/M: EA; Cap_F: 0.000000018; Tolerance_%: 5; VDC_V: 50; Value2: 50V; TaMin_C: -55; TaMax_C: 125; Cap_Case: 1206; SizeArea_mm2: 5.12; SizeAreaWB_mm2: 10.92; SizeX_mm: 3.2; SizeY_mm: 1.6; SizeZ_mm: 1.35; AEC Category: Q200
signal-integrity model Cap
simulation model Cap
footprint 1206
footprint 1206M
footprint 1206L
pins: 1, 2

## GRM3195C1H203JA01D
designator C?  ValueDisplayed: 0.02µF  (hidden comment: GRM3195C1H203JA01D)
CAP, CERM, 0.02 µF, 50 V,+/- 5%, C0G/NP0, 1206; Manufacturer: MuRata; Polarized: N; CompType: Capacitor; Value: 0.02uF; U/M: EA; Cap_F: 0.00000002; Tolerance_%: 5; VDC_V: 50; Value2: 50V; TaMin_C: -55; TaMax_C: 125; Cap_Case: 1206; SizeArea_mm2: 5.12; SizeAreaWB_mm2: 10.92; SizeX_mm: 3.2; SizeY_mm: 1.6; SizeZ_mm: 1.35; AEC Category: Q200
signal-integrity model Cap
simulation model Cap
footprint 1206
footprint 1206M
footprint 1206L
pins: 1, 2

## GRM3195C1H222JA01D
designator C?  ValueDisplayed: 2200pF  (hidden comment: GRM3195C1H222JA01D)
CAP, CERM, 2200 pF, 50 V,+/- 5%, C0G/NP0, 1206; Manufacturer: MuRata; Polarized: N; CompType: Capacitor; Value: 2200pF; U/M: EA; Cap_F: 0.0000000022; Tolerance_%: 5; VDC_V: 50; Value2: 50V; TaMin_C: -55; TaMax_C: 125; Cap_Case: 1206; SizeArea_mm2: 5.12; SizeAreaWB_mm2: 10.92; SizeX_mm: 3.2; SizeY_mm: 1.6; SizeZ_mm: 1.35; AEC Category: Q200
signal-integrity model Cap
simulation model Cap
footprint 1206
footprint 1206M
footprint 1206L
pins: 1, 2

## GRM3195C1H223JA01D
designator C?  ValueDisplayed: 0.022µF  (hidden comment: GRM3195C1H223JA01D)
CAP, CERM, 0.022 µF, 50 V,+/- 5%, C0G/NP0, 1206; Manufacturer: MuRata; Polarized: N; CompType: Capacitor; Value: 0.022uF; U/M: EA; Cap_F: 0.000000022; Tolerance_%: 5; VDC_V: 50; Value2: 50V; TaMin_C: -55; TaMax_C: 125; Cap_Case: 1206; SizeArea_mm2: 5.12; SizeAreaWB_mm2: 10.92; SizeX_mm: 3.2; SizeY_mm: 1.6; SizeZ_mm: 1.35; AEC Category: Q200
signal-integrity model Cap
simulation model Cap
footprint 1206
footprint 1206M
footprint 1206L
pins: 1, 2

## GRM3195C1H273JA01D
designator C?  ValueDisplayed: 0.027µF  (hidden comment: GRM3195C1H273JA01D)
CAP, CERM, 0.027 µF, 50 V,+/- 5%, C0G/NP0, 1206; Manufacturer: MuRata; Polarized: N; CompType: Capacitor; Value: 0.027uF; U/M: EA; Cap_F: 0.000000027; Tolerance_%: 5; VDC_V: 50; Value2: 50V; TaMin_C: -55; TaMax_C: 125; Cap_Case: 1206; SizeArea_mm2: 5.12; SizeAreaWB_mm2: 10.92; SizeX_mm: 3.2; SizeY_mm: 1.6; SizeZ_mm: 1.35; AEC Category: Q200
signal-integrity model Cap
simulation model Cap
footprint 1206
footprint 1206M
footprint 1206L
pins: 1, 2

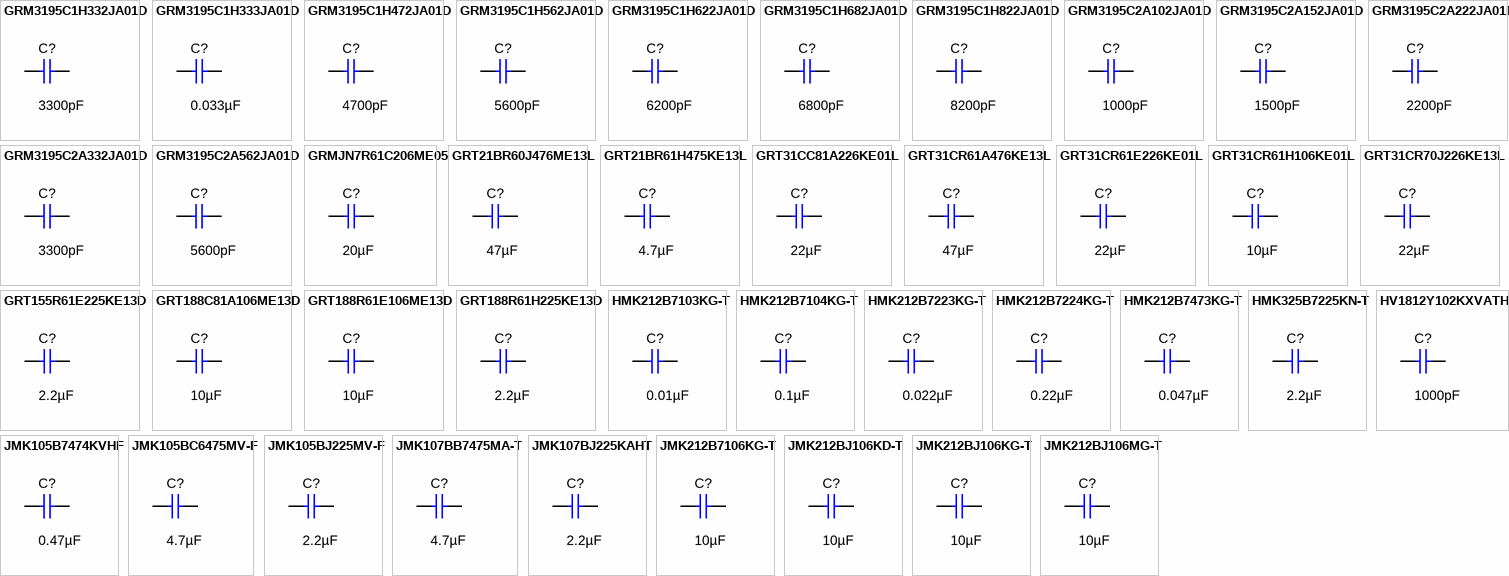
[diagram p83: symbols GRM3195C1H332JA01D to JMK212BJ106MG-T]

## GRM3195C1H332JA01D
designator C?  ValueDisplayed: 3300pF  (hidden comment: GRM3195C1H332JA01D)
CAP, CERM, 3300 pF, 50 V,+/- 5%, C0G/NP0, 1206; Manufacturer: MuRata; Polarized: N; CompType: Capacitor; Value: 3300pF; U/M: EA; Cap_F: 0.0000000033; Tolerance_%: 5; VDC_V: 50; Value2: 50V; TaMin_C: -55; TaMax_C: 125; Cap_Case: 1206; SizeArea_mm2: 5.12; SizeAreaWB_mm2: 10.92; SizeX_mm: 3.2; SizeY_mm: 1.6; SizeZ_mm: 1.35; AEC Category: Q200
signal-integrity model Cap
simulation model Cap
footprint 1206
footprint 1206M
footprint 1206L
pins: 1, 2

## GRM3195C1H333JA01D
designator C?  ValueDisplayed: 0.033µF  (hidden comment: GRM3195C1H333JA01D)
CAP, CERM, 0.033 µF, 50 V,+/- 5%, C0G/NP0, 1206; Manufacturer: MuRata; Polarized: N; CompType: Capacitor; Value: 0.033uF; U/M: EA; Cap_F: 0.000000033; Tolerance_%: 5; VDC_V: 50; Value2: 50V; TaMin_C: -55; TaMax_C: 125; Cap_Case: 1206; SizeArea_mm2: 5.12; SizeAreaWB_mm2: 10.92; SizeX_mm: 3.2; SizeY_mm: 1.6; SizeZ_mm: 1.35; AEC Category: Q200
signal-integrity model Cap
simulation model Cap
footprint 1206
footprint 1206M
footprint 1206L
pins: 1, 2

## GRM3195C1H472JA01D
designator C?  ValueDisplayed: 4700pF  (hidden comment: GRM3195C1H472JA01D)
CAP, CERM, 4700 pF, 50 V,+/- 5%, C0G/NP0, 1206; Manufacturer: MuRata; Polarized: N; CompType: Capacitor; Value: 4700pF; U/M: EA; Cap_F: 0.0000000047; Tolerance_%: 5; VDC_V: 50; Value2: 50V; TaMin_C: -55; TaMax_C: 125; Cap_Case: 1206; SizeArea_mm2: 5.12; SizeAreaWB_mm2: 10.92; SizeX_mm: 3.2; SizeY_mm: 1.6; SizeZ_mm: 1.35; AEC Category: Q200
signal-integrity model Cap
simulation model Cap
footprint 1206
footprint 1206M
footprint 1206L
pins: 1, 2

## GRM3195C1H562JA01D
designator C?  ValueDisplayed: 5600pF  (hidden comment: GRM3195C1H562JA01D)
CAP, CERM, 5600 pF, 50 V,+/- 5%, C0G/NP0, 1206; Manufacturer: MuRata; Polarized: N; CompType: Capacitor; Value: 5600pF; U/M: EA; Cap_F: 0.0000000056; Tolerance_%: 5; VDC_V: 50; Value2: 50V; TaMin_C: -55; TaMax_C: 125; Cap_Case: 1206; SizeArea_mm2: 5.12; SizeAreaWB_mm2: 10.92; SizeX_mm: 3.2; SizeY_mm: 1.6; SizeZ_mm: 1.35; AEC Category: Q200
signal-integrity model Cap
simulation model Cap
footprint 1206
footprint 1206M
footprint 1206L
pins: 1, 2

## GRM3195C1H622JA01D
designator C?  ValueDisplayed: 6200pF  (hidden comment: GRM3195C1H622JA01D)
CAP, CERM, 6200 pF, 50 V,+/- 5%, C0G/NP0, 1206; Manufacturer: MuRata; Polarized: N; CompType: Capacitor; Value: 6200pF; U/M: EA; Cap_F: 0.0000000062; Tolerance_%: 5; VDC_V: 50; Value2: 50V; TaMin_C: -55; TaMax_C: 125; Cap_Case: 1206; SizeArea_mm2: 5.12; SizeAreaWB_mm2: 10.92; SizeX_mm: 3.2; SizeY_mm: 1.6; SizeZ_mm: 1.35; AEC Category: Q200
signal-integrity model Cap
simulation model Cap
footprint 1206
footprint 1206M
footprint 1206L
pins: 1, 2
